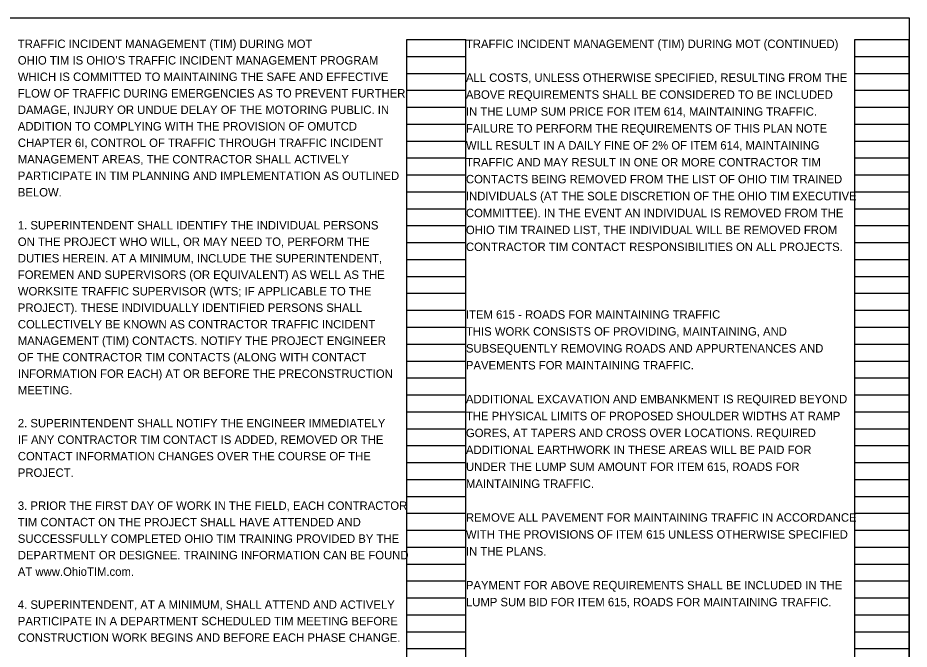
# Model space of a CAD drawing. Extents: x 1820207 to 1820557, y 740216 to 740315.
# Drawn here: x 1820384.66 to 1820399.42, y 740265.29 to 740275.74 of the extents above; entities that cross this region are included whole.
import ezdxf

# ---------------------------------------------------------------- set-up
doc = ezdxf.new("R2010")
doc.units = 0
for name, color, linetype in [('SC_Scratch1', 7, 'Continuous'), ('SC_Scratch2', 7, 'Continuous'), ('SH_Text', 7, 'Continuous')]:
    doc.layers.add(name, color=color, linetype=linetype)

msp = doc.modelspace()

# ---------------------------------------------------------------- linework, layer by layer
at = {"layer": 'SC_Scratch1'}
for p, q in [((1820391.101, 740255.222), (1820391.101, 740275.382)), ((1820391.101, 740275.382), (1820392.081, 740275.382)), ((1820392.081, 740255.222), (1820392.081, 740275.382)), ((1820398.521, 740255.222), (1820398.521, 740275.382)), ((1820398.521, 740275.382), (1820399.421, 740275.382)), ((1820399.421, 740255.222), (1820399.421, 740275.382)), ((1820391.101, 740275.102), (1820392.081, 740275.102)), ((1820398.521, 740275.102), (1820399.421, 740275.102)), ((1820391.101, 740274.822), (1820392.081, 740274.822)), ((1820398.521, 740274.822), (1820399.421, 740274.822)), ((1820391.101, 740274.542), (1820392.081, 740274.542)), ((1820398.521, 740274.542), (1820399.421, 740274.542)), ((1820391.101, 740274.262), (1820392.081, 740274.262)), ((1820398.521, 740274.262), (1820399.421, 740274.262)), ((1820391.101, 740273.982), (1820392.081, 740273.982)), ((1820398.521, 740273.982), (1820399.421, 740273.982)), ((1820391.101, 740273.702), (1820392.081, 740273.702)), ((1820398.521, 740273.702), (1820399.421, 740273.702)), ((1820391.101, 740273.422), (1820392.081, 740273.422)), ((1820398.521, 740273.422), (1820399.421, 740273.422)), ((1820391.101, 740273.142), (1820392.081, 740273.142)), ((1820398.521, 740273.142), (1820399.421, 740273.142)), ((1820391.101, 740272.862), (1820392.081, 740272.862)), ((1820398.521, 740272.862), (1820399.421, 740272.862)), ((1820391.101, 740272.582), (1820392.081, 740272.582)), ((1820398.521, 740272.582), (1820399.421, 740272.582)), ((1820391.101, 740272.302), (1820392.081, 740272.302)), ((1820398.521, 740272.302), (1820399.421, 740272.302)), ((1820391.101, 740272.022), (1820392.081, 740272.022)), ((1820398.521, 740272.022), (1820399.421, 740272.022)), ((1820391.101, 740271.742), (1820392.081, 740271.742)), ((1820398.521, 740271.742), (1820399.421, 740271.742)), ((1820391.101, 740271.462), (1820392.081, 740271.462)), ((1820398.521, 740271.462), (1820399.421, 740271.462)), ((1820391.101, 740271.182), (1820392.081, 740271.182)), ((1820398.521, 740271.182), (1820399.421, 740271.182)), ((1820391.101, 740270.902), (1820392.081, 740270.902)), ((1820398.521, 740270.902), (1820399.421, 740270.902)), ((1820391.101, 740270.622), (1820392.081, 740270.622)), ((1820398.521, 740270.622), (1820399.421, 740270.622)), ((1820391.101, 740270.342), (1820392.081, 740270.342)), ((1820398.521, 740270.342), (1820399.421, 740270.342)), ((1820391.101, 740270.062), (1820392.081, 740270.062)), ((1820398.521, 740270.062), (1820399.421, 740270.062)), ((1820391.101, 740269.782), (1820392.081, 740269.782)), ((1820398.521, 740269.782), (1820399.421, 740269.782)), ((1820391.101, 740269.502), (1820392.081, 740269.502)), ((1820398.521, 740269.502), (1820399.421, 740269.502)), ((1820391.101, 740269.222), (1820392.081, 740269.222)), ((1820398.521, 740269.222), (1820399.421, 740269.222)), ((1820391.101, 740268.942), (1820392.081, 740268.942)), ((1820398.521, 740268.942), (1820399.421, 740268.942)), ((1820391.101, 740268.662), (1820392.081, 740268.662)), ((1820398.521, 740268.662), (1820399.421, 740268.662)), ((1820391.101, 740268.382), (1820392.081, 740268.382)), ((1820398.521, 740268.382), (1820399.421, 740268.382)), ((1820391.101, 740268.102), (1820392.081, 740268.102)), ((1820398.521, 740268.102), (1820399.421, 740268.102)), ((1820391.101, 740267.822), (1820392.081, 740267.822)), ((1820398.521, 740267.822), (1820399.421, 740267.822)), ((1820391.101, 740267.542), (1820392.081, 740267.542)), ((1820398.521, 740267.542), (1820399.421, 740267.542)), ((1820391.101, 740267.262), (1820392.081, 740267.262)), ((1820398.521, 740267.262), (1820399.421, 740267.262)), ((1820391.101, 740266.982), (1820392.081, 740266.982)), ((1820398.521, 740266.982), (1820399.421, 740266.982)), ((1820391.101, 740266.702), (1820392.081, 740266.702)), ((1820398.521, 740266.702), (1820399.421, 740266.702)), ((1820391.101, 740266.422), (1820392.081, 740266.422)), ((1820398.521, 740266.422), (1820399.421, 740266.422)), ((1820391.101, 740266.142), (1820392.081, 740266.142)), ((1820398.521, 740266.142), (1820399.421, 740266.142)), ((1820391.101, 740265.862), (1820392.081, 740265.862)), ((1820398.521, 740265.862), (1820399.421, 740265.862)), ((1820391.101, 740265.582), (1820392.081, 740265.582)), ((1820398.521, 740265.582), (1820399.421, 740265.582)), ((1820391.101, 740265.302), (1820392.081, 740265.302)), ((1820398.521, 740265.302), (1820399.421, 740265.302))]:
    msp.add_line(p, q, dxfattribs=at)
at = {"layer": 'SC_Scratch2'}
msp.add_lwpolyline([(1820368.921, 740275.742), (1820399.421, 740275.742), (1820399.421, 740254.742), (1820368.921, 740254.742)], close=True, dxfattribs=at)

# ---------------------------------------------------------------- texts
at = {"layer": 'SH_Text'}
for s, p in [('TRAFFIC INCIDENT MANAGEMENT (TIM) DURING MOT', (1820384.661, 740275.242)), ('TRAFFIC INCIDENT MANAGEMENT (TIM) DURING MOT (CONTINUED)', (1820392.081, 740275.242)), ('OHIO TIM IS OHIO’S TRAFFIC INCIDENT MANAGEMENT PROGRAM ', (1820384.661, 740274.969)), ('WHICH IS COMMITTED TO MAINTAINING THE SAFE AND EFFECTIVE ', (1820384.661, 740274.696)), ('ALL COSTS, UNLESS OTHERWISE SPECIFIED, RESULTING FROM THE ', (1820392.081, 740274.682)), ('FLOW OF TRAFFIC DURING EMERGENCIES AS TO PREVENT FURTHER ', (1820384.661, 740274.423)), ('ABOVE REQUIREMENTS SHALL BE CONSIDERED TO BE INCLUDED ', (1820392.081, 740274.402)), ('DAMAGE, INJURY OR UNDUE DELAY OF THE MOTORING PUBLIC. IN ', (1820384.661, 740274.15)), ('IN THE LUMP SUM PRICE FOR ITEM 614, MAINTAINING TRAFFIC. ', (1820392.081, 740274.122)), ('ADDITION TO COMPLYING WITH THE PROVISION OF OMUTCD ', (1820384.661, 740273.877)), ('FAILURE TO PERFORM THE REQUIREMENTS OF THIS PLAN NOTE ', (1820392.081, 740273.842)), ('CHAPTER 6I, CONTROL OF TRAFFIC THROUGH TRAFFIC INCIDENT ', (1820384.661, 740273.604)), ('WILL RESULT IN A DAILY FINE OF 2% OF ITEM 614, MAINTAINING ', (1820392.081, 740273.562)), ('MANAGEMENT AREAS, THE CONTRACTOR SHALL ACTIVELY ', (1820384.661, 740273.331)), ('TRAFFIC AND MAY RESULT IN ONE OR MORE CONTRACTOR TIM ', (1820392.081, 740273.282)), ('PARTICIPATE IN TIM PLANNING AND IMPLEMENTATION AS OUTLINED ', (1820384.661, 740273.058)), ('CONTACTS BEING REMOVED FROM THE LIST OF OHIO TIM TRAINED ', (1820392.081, 740273.002)), ('BELOW.', (1820384.661, 740272.785)), ('INDIVIDUALS (AT THE SOLE DISCRETION OF THE OHIO TIM EXECUTIVE ', (1820392.081, 740272.722)), ('COMMITTEE). IN THE EVENT AN INDIVIDUAL IS REMOVED FROM THE ', (1820392.081, 740272.442)), ('1. SUPERINTENDENT SHALL IDENTIFY THE INDIVIDUAL PERSONS ', (1820384.661, 740272.239)), ('OHIO TIM TRAINED LIST, THE INDIVIDUAL WILL BE REMOVED FROM ', (1820392.081, 740272.162)), ('ON THE PROJECT WHO WILL, OR MAY NEED TO, PERFORM THE ', (1820384.661, 740271.966)), ('CONTRACTOR TIM CONTACT RESPONSIBILITIES ON ALL PROJECTS.', (1820392.081, 740271.882)), ('DUTIES HEREIN. AT A MINIMUM, INCLUDE THE SUPERINTENDENT, ', (1820384.661, 740271.693)), ('FOREMEN AND SUPERVISORS (OR EQUIVALENT) AS WELL AS THE ', (1820384.661, 740271.42)), ('WORKSITE TRAFFIC SUPERVISOR (WTS; IF APPLICABLE TO THE ', (1820384.661, 740271.147)), ('PROJECT). THESE INDIVIDUALLY IDENTIFIED PERSONS SHALL ', (1820384.661, 740270.874)), ('ITEM 615 - ROADS FOR MAINTAINING TRAFFIC', (1820392.081, 740270.762)), ('COLLECTIVELY BE KNOWN AS CONTRACTOR TRAFFIC INCIDENT ', (1820384.661, 740270.601)), ('THIS WORK CONSISTS OF PROVIDING, MAINTAINING, AND', (1820392.081, 740270.482)), ('MANAGEMENT (TIM) CONTACTS. NOTIFY THE PROJECT ENGINEER ', (1820384.661, 740270.328)), ('SUBSEQUENTLY REMOVING ROADS AND APPURTENANCES AND ', (1820392.081, 740270.202)), ('OF THE CONTRACTOR TIM CONTACTS (ALONG WITH CONTACT ', (1820384.661, 740270.055)), ('INFORMATION FOR EACH) AT OR BEFORE THE PRECONSTRUCTION ', (1820384.661, 740269.782)), ('PAVEMENTS FOR MAINTAINING TRAFFIC.', (1820392.081, 740269.922)), ('MEETING.', (1820384.661, 740269.509)), ('ADDITIONAL EXCAVATION AND EMBANKMENT IS REQUIRED BEYOND', (1820392.081, 740269.362)), ('THE PHYSICAL LIMITS OF PROPOSED SHOULDER WIDTHS AT RAMP', (1820392.081, 740269.082)), ('2. SUPERINTENDENT SHALL NOTIFY THE ENGINEER IMMEDIATELY ', (1820384.661, 740268.963)), ('GORES, AT TAPERS AND CROSS OVER LOCATIONS. REQUIRED ', (1820392.081, 740268.802)), ('IF ANY CONTRACTOR TIM CONTACT IS ADDED, REMOVED OR THE ', (1820384.661, 740268.69)), ('ADDITIONAL EARTHWORK IN THESE AREAS WILL BE PAID FOR ', (1820392.081, 740268.522)), ('CONTACT INFORMATION CHANGES OVER THE COURSE OF THE ', (1820384.661, 740268.417)), ('UNDER THE LUMP SUM AMOUNT FOR ITEM 615, ROADS FOR ', (1820392.081, 740268.242)), ('PROJECT.', (1820384.661, 740268.144)), ('MAINTAINING TRAFFIC.', (1820392.081, 740267.962)), ('3. PRIOR THE FIRST DAY OF WORK IN THE FIELD, EACH CONTRACTOR ', (1820384.661, 740267.598)), ('TIM CONTACT ON THE PROJECT SHALL HAVE ATTENDED AND ', (1820384.661, 740267.325)), ('REMOVE ALL PAVEMENT FOR MAINTAINING TRAFFIC IN ACCORDANCE', (1820392.081, 740267.402)), ('SUCCESSFULLY COMPLETED OHIO TIM TRAINING PROVIDED BY THE ', (1820384.661, 740267.052)), ('WITH THE PROVISIONS OF ITEM 615 UNLESS OTHERWISE SPECIFIED ', (1820392.081, 740267.122)), ('IN THE PLANS.', (1820392.081, 740266.842)), ('DEPARTMENT OR DESIGNEE. TRAINING INFORMATION CAN BE FOUND ', (1820384.661, 740266.779)), ('AT www.OhioTIM.com.', (1820384.661, 740266.506)), ('PAYMENT FOR ABOVE REQUIREMENTS SHALL BE INCLUDED IN THE ', (1820392.081, 740266.282)), ('4. SUPERINTENDENT, AT A MINIMUM, SHALL ATTEND AND ACTIVELY ', (1820384.661, 740265.96)), ('LUMP SUM BID FOR ITEM 615, ROADS FOR MAINTAINING TRAFFIC.', (1820392.081, 740266.002)), ('PARTICIPATE IN A DEPARTMENT SCHEDULED TIM MEETING BEFORE ', (1820384.661, 740265.687)), ('CONSTRUCTION WORK BEGINS AND BEFORE EACH PHASE CHANGE. ', (1820384.661, 740265.414))]:
    msp.add_text(s, height=0.14, dxfattribs=at).set_placement(p)

doc.saveas('drawing.dxf')
